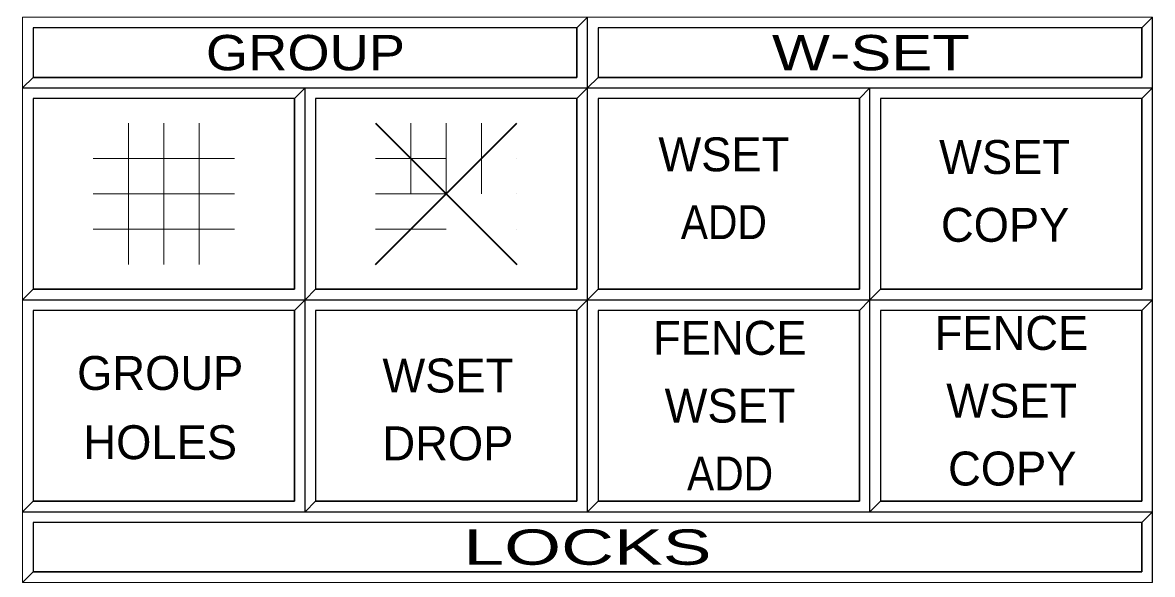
# Model space of a CAD drawing. Extents: x 95906.8 to 95923.6, y 90964.8 to 90972.8.
# Drawn here: x 95916.332 to 95917.932, y 90969.573 to 90970.354 of the extents above; entities that cross this region are included whole.
import ezdxf
from ezdxf.enums import TextEntityAlignment as Align

# ---------------------------------------------------------------- set-up
doc = ezdxf.new("R2010")
doc.units = 0
doc.header["$LTSCALE"] = 0.019
doc.linetypes.add('MEDIUM_DASHED', pattern=[4.5, 3, -1.5])
for name, color, linetype, lineweight in [('11', 7, 'Continuous', 25), ('12', 7, 'Continuous', 25), ('16', 7, 'Continuous', 25), ('2', 7, 'Continuous', 13), ('21', 7, 'Continuous', 25), ('3', 7, 'Continuous', 25), ('6', 7, 'Continuous', 25), ('7', 7, 'Continuous', 35)]:
    doc.layers.add(name, color=color, linetype=linetype, lineweight=lineweight)

msp = doc.modelspace()

# ---------------------------------------------------------------- linework, layer by layer
at = {"layer": '11'}
for points in [[(95916.7473, 90969.9767), (95917.1173, 90969.9767), (95917.1173, 90970.2467), (95916.7473, 90970.2467)], [(95917.1473, 90969.9767), (95917.5173, 90969.9767), (95917.5173, 90970.2467), (95917.1473, 90970.2467)], [(95917.5473, 90969.9767), (95917.9173, 90969.9767), (95917.9173, 90970.2467), (95917.5473, 90970.2467)], [(95916.3473, 90969.6767), (95916.7173, 90969.6767), (95916.7173, 90969.9467), (95916.3473, 90969.9467)], [(95916.7473, 90969.6767), (95917.1173, 90969.6767), (95917.1173, 90969.9467), (95916.7473, 90969.9467)], [(95917.1473, 90969.6767), (95917.5173, 90969.6767), (95917.5173, 90969.9467), (95917.1473, 90969.9467)], [(95917.5473, 90969.6767), (95917.9173, 90969.6767), (95917.9173, 90969.9467), (95917.5473, 90969.9467)]]:
    msp.add_lwpolyline(points, close=True, dxfattribs=at)
at = {"layer": '12'}
msp.add_lwpolyline([(95916.3473, 90969.9767), (95916.7173, 90969.9767), (95916.7173, 90970.2467), (95916.3473, 90970.2467)], close=True, dxfattribs=at)
at = {"layer": '16'}
for points in [[(95916.3473, 90970.2767), (95917.1173, 90970.2767), (95917.1173, 90970.3467), (95916.3473, 90970.3467)], [(95917.1473, 90970.2767), (95917.9173, 90970.2767), (95917.9173, 90970.3467), (95917.1473, 90970.3467)]]:
    msp.add_lwpolyline(points, close=True, dxfattribs=at)
at = {"layer": '2'}
for points in [[(95916.3323, 90970.3617), (95916.3323, 90970.2617), (95916.3473, 90970.2767), (95916.3473, 90970.3467), (95917.1173, 90970.3467), (95917.1323, 90970.3617)], [(95917.1323, 90970.3617), (95917.1323, 90970.2617), (95917.1473, 90970.2767), (95917.1473, 90970.3467), (95917.9173, 90970.3467), (95917.9323, 90970.3617)], [(95916.3323, 90970.2617), (95916.3323, 90969.9617), (95916.3473, 90969.9767), (95916.3473, 90970.2467), (95916.7173, 90970.2467), (95916.7323, 90970.2617)], [(95916.7323, 90970.2617), (95916.7323, 90969.9617), (95916.7473, 90969.9767), (95916.7473, 90970.2467), (95917.1173, 90970.2467), (95917.1323, 90970.2617)], [(95917.1323, 90970.2617), (95917.1323, 90969.9617), (95917.1473, 90969.9767), (95917.1473, 90970.2467), (95917.5173, 90970.2467), (95917.5323, 90970.2617)], [(95917.5323, 90970.2617), (95917.5323, 90969.9617), (95917.5473, 90969.9767), (95917.5473, 90970.2467), (95917.9173, 90970.2467), (95917.9323, 90970.2617)], [(95916.3323, 90969.9617), (95916.3323, 90969.6617), (95916.3473, 90969.6767), (95916.3473, 90969.9467), (95916.7173, 90969.9467), (95916.7323, 90969.9617)], [(95916.7323, 90969.9617), (95916.7323, 90969.6617), (95916.7473, 90969.6767), (95916.7473, 90969.9467), (95917.1173, 90969.9467), (95917.1323, 90969.9617)], [(95917.1323, 90969.9617), (95917.1323, 90969.6617), (95917.1473, 90969.6767), (95917.1473, 90969.9467), (95917.5173, 90969.9467), (95917.5323, 90969.9617)], [(95917.5323, 90969.9617), (95917.5323, 90969.6617), (95917.5473, 90969.6767), (95917.5473, 90969.9467), (95917.9173, 90969.9467), (95917.9323, 90969.9617)], [(95916.3323, 90969.6617), (95916.3323, 90969.5617), (95916.3473, 90969.5767), (95916.3473, 90969.6467), (95917.9173, 90969.6467), (95917.9323, 90969.6617)]]:
    msp.add_lwpolyline(points, close=True, dxfattribs=at)
at = {"layer": '21'}
msp.add_lwpolyline([(95916.3473, 90969.5767), (95917.9173, 90969.5767), (95917.9173, 90969.6467), (95916.3473, 90969.6467)], close=True, dxfattribs=at)
at = {"layer": '3'}
for points in [[(95916.3323, 90970.2617), (95917.1323, 90970.2617), (95917.1323, 90970.3617), (95917.1173, 90970.3467), (95917.1173, 90970.2767), (95916.3473, 90970.2767)], [(95917.1323, 90970.2617), (95917.9323, 90970.2617), (95917.9323, 90970.3617), (95917.9173, 90970.3467), (95917.9173, 90970.2767), (95917.1473, 90970.2767)], [(95916.3323, 90969.9617), (95916.7323, 90969.9617), (95916.7323, 90970.2617), (95916.7173, 90970.2467), (95916.7173, 90969.9767), (95916.3473, 90969.9767)], [(95916.7323, 90969.9617), (95917.1323, 90969.9617), (95917.1323, 90970.2617), (95917.1173, 90970.2467), (95917.1173, 90969.9767), (95916.7473, 90969.9767)], [(95917.1323, 90969.9617), (95917.5323, 90969.9617), (95917.5323, 90970.2617), (95917.5173, 90970.2467), (95917.5173, 90969.9767), (95917.1473, 90969.9767)], [(95917.5323, 90969.9617), (95917.9323, 90969.9617), (95917.9323, 90970.2617), (95917.9173, 90970.2467), (95917.9173, 90969.9767), (95917.5473, 90969.9767)], [(95916.3323, 90969.6617), (95916.7323, 90969.6617), (95916.7323, 90969.9617), (95916.7173, 90969.9467), (95916.7173, 90969.6767), (95916.3473, 90969.6767)], [(95916.7323, 90969.6617), (95917.1323, 90969.6617), (95917.1323, 90969.9617), (95917.1173, 90969.9467), (95917.1173, 90969.6767), (95916.7473, 90969.6767)], [(95917.1323, 90969.6617), (95917.5323, 90969.6617), (95917.5323, 90969.9617), (95917.5173, 90969.9467), (95917.5173, 90969.6767), (95917.1473, 90969.6767)], [(95917.5323, 90969.6617), (95917.9323, 90969.6617), (95917.9323, 90969.9617), (95917.9173, 90969.9467), (95917.9173, 90969.6767), (95917.5473, 90969.6767)], [(95916.3323, 90969.5617), (95917.9323, 90969.5617), (95917.9323, 90969.6617), (95917.9173, 90969.6467), (95917.9173, 90969.5767), (95916.3473, 90969.5767)]]:
    msp.add_lwpolyline(points, close=True, dxfattribs=at)
at = {"layer": '6', "lineweight": 13}
for p, q in [((95916.4823, 90970.2117), (95916.4823, 90970.0117)), ((95916.4823, 90970.2117), (95916.4823, 90970.0117)), ((95916.5323, 90970.2117), (95916.5323, 90970.0117)), ((95916.5323, 90970.2117), (95916.5323, 90970.0117)), ((95916.5823, 90970.2117), (95916.5823, 90970.0117)), ((95916.5823, 90970.2117), (95916.5823, 90970.0117)), ((95916.4323, 90970.1617), (95916.6323, 90970.1617)), ((95916.4323, 90970.1617), (95916.6323, 90970.1617)), ((95916.4323, 90970.1117), (95916.6323, 90970.1117)), ((95916.4323, 90970.1117), (95916.6323, 90970.1117)), ((95916.4323, 90970.0617), (95916.6323, 90970.0617)), ((95916.4323, 90970.0617), (95916.6323, 90970.0617))]:
    msp.add_line(p, q, dxfattribs=at)
at = {"layer": '6', "lineweight": 35}
for p, q in [((95916.8323, 90970.0117), (95917.0323, 90970.2117)), ((95916.8323, 90970.2117), (95917.0323, 90970.0117)), ((95916.8323, 90970.0117), (95917.0323, 90970.2117)), ((95916.8323, 90970.2117), (95917.0323, 90970.0117))]:
    msp.add_line(p, q, dxfattribs=at)
at = {"layer": '6', "linetype": 'MEDIUM_DASHED', "lineweight": 13}
for p, q in [((95916.8823, 90970.2117), (95916.8823, 90970.0117)), ((95916.8823, 90970.2117), (95916.8823, 90970.0117)), ((95916.9323, 90970.2117), (95916.9323, 90970.0117)), ((95916.9323, 90970.2117), (95916.9323, 90970.0117)), ((95916.9823, 90970.2117), (95916.9823, 90970.0117)), ((95916.9823, 90970.2117), (95916.9823, 90970.0117)), ((95916.8323, 90970.1617), (95917.0323, 90970.1617)), ((95916.8323, 90970.1617), (95917.0323, 90970.1617)), ((95916.8323, 90970.1117), (95917.0323, 90970.1117)), ((95916.8323, 90970.1117), (95917.0323, 90970.1117)), ((95916.8323, 90970.0617), (95917.0323, 90970.0617)), ((95916.8323, 90970.0617), (95917.0323, 90970.0617))]:
    msp.add_line(p, q, dxfattribs=at)

# ---------------------------------------------------------------- texts
at = {"layer": '21', "width": 1.55}
msp.add_text('         LOCKS         ', height=0.04999, dxfattribs=at).set_placement((95917.1323, 90969.5867), align=Align.CENTER)
at = {"layer": '6'}
for s, height, p in [('WSET', 0.048, (95917.3254, 90970.1437)), ('WSET', 0.048, (95917.723, 90970.1399)), ('COPY', 0.048, (95917.7238, 90970.0439)), ('FENCE', 0.048, (95917.7328, 90969.8909)), ('FENCE', 0.048, (95917.3339, 90969.8839)), ('GROUP', 0.04799, (95916.5272, 90969.8342)), ('WSET', 0.048, (95916.9346, 90969.8306)), ('WSET', 0.048, (95917.7331, 90969.7949)), ('WSET', 0.048, (95917.3342, 90969.7879)), ('HOLES', 0.04799, (95916.5272, 90969.7362)), ('DROP', 0.048, (95916.9346, 90969.7346)), ('COPY', 0.048, (95917.7339, 90969.6989))]:
    msp.add_text(s, height=height, dxfattribs=at).set_placement(p, align=Align.CENTER)
at = {"layer": '6', "width": 0.9}
for p in [(95917.3254, 90970.0477), (95917.3342, 90969.6919)]:
    msp.add_text('ADD', height=0.048, dxfattribs=at).set_placement(p, align=Align.CENTER)
at = {"layer": '7'}
for s, width, p in [('GROUP', 1.15, (95916.7329, 90970.2867)), ('W-SET', 1.3, (95917.5335, 90970.2867))]:
    msp.add_text(s, height=0.04999, dxfattribs=dict(at, width=width)).set_placement(p, align=Align.CENTER)

doc.saveas('drawing.dxf')
